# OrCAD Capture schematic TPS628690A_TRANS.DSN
size D; title: TPS628690A 2.4-V to 5.5-V Input, 6-A Synchronous Step-Down; rev: 1.1; note: Datasheet: SLVSFS3A        EVM: SLUUC88A
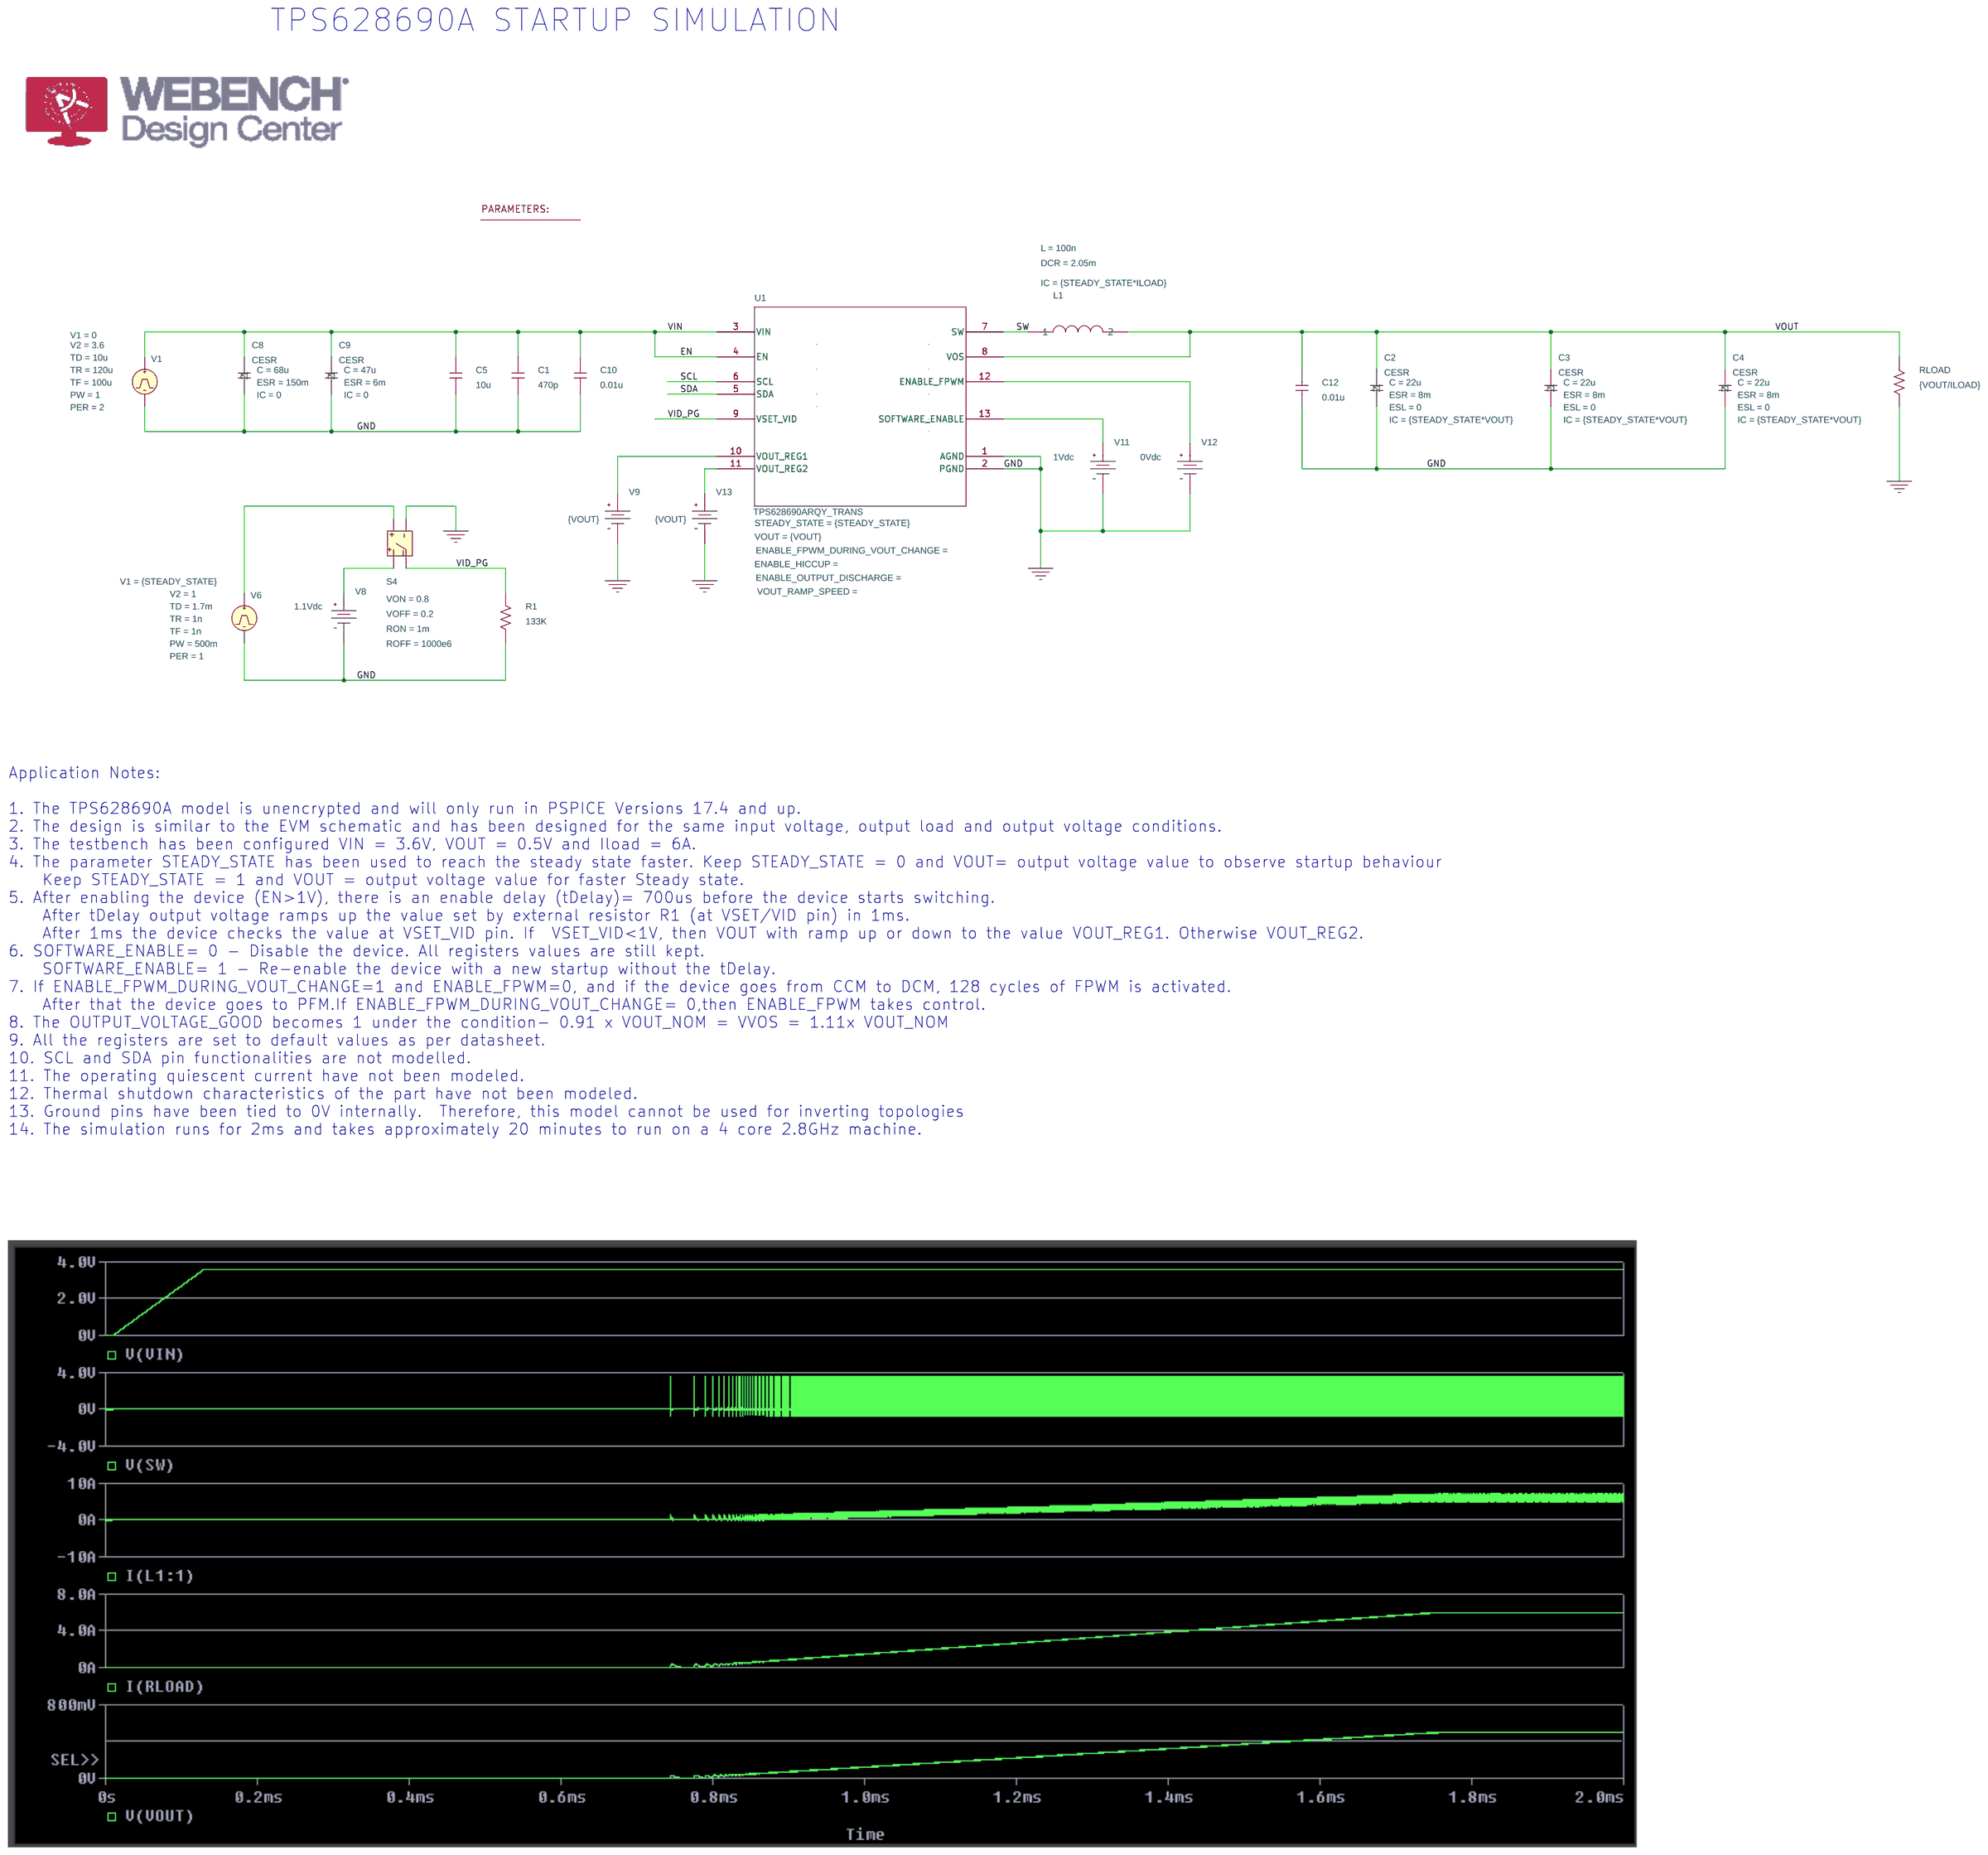
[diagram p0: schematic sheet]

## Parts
6  PARAM
C1  470p  [RAD/CK05]
C2  CESR
C3  CESR
C4  CESR
C5  10u  [RAD/CK05]
C8  CESR
C9  CESR
C10  0.01u  [RAD/CK05]
C12  0.01u  [RAD/CK05]
L1  LDCR
R1  133K  [AX/RC05]
RLOAD  {VOUT/ILOAD}  [AX/RC05]
S4  S
U1  TPS628690ARQY_TRANS  [RQY0009A-MFG]
V1  VPULSE
V6  VPULSE
V8  VDC
V9  VDC
V11  VDC
V12  VDC
V13  VDC

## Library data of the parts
6 = PARAM: STEADY_STATE: 0; VOUT: 0.5
C1 C5 C10 C12 = C
C2 = CESR_4: C: 22u; ESL: 0; ESR: 8m; IC: {STEADY_STATE*VOUT}; PSpiceTemplate: X^@REFDES %1 %2 @MODEL PARAMS: ?C|C=@C||C=10U| ?ESR|ESR=@ESR||ESR=2M| ?ESL|ESL=@ESL||ESL=1N| ?IC|IC=@IC||IC=0|
C3 = CESR_3: C: 22u; ESL: 0; ESR: 8m; IC: {STEADY_STATE*VOUT}; PSpiceTemplate: X^@REFDES %1 %2 @MODEL PARAMS: ?C|C=@C||C=10U| ?ESR|ESR=@ESR||ESR=2M| ?ESL|ESL=@ESL||ESL=1N| ?IC|IC=@IC||IC=0|
C4 = CESR: C: 22u; ESL: 0; ESR: 8m; IC: {STEADY_STATE*VOUT}; PSpiceTemplate: X^@REFDES %1 %2 @MODEL PARAMS: ?C|C=@C||C=10U| ?ESR|ESR=@ESR||ESR=2M| ?ESL|ESL=@ESL||ESL=1N| ?IC|IC=@IC||IC=0|
C8 = CESR_1: C: 68u; ESR: 150m; IC: 0; PSpiceTemplate: X^@REFDES %1 %2 @MODEL PARAMS: ?C|C=@C||C=10U| ?ESR|ESR=@ESR||ESR=2M| ?ESL|ESL=@ESL||ESL=1N| ?IC|IC=@IC||IC=0|
C9 = CESR_2: C: 47u; ESR: 6m; IC: 0; PSpiceTemplate: X^@REFDES %1 %2 @MODEL PARAMS: ?C|C=@C||C=10U| ?ESR|ESR=@ESR||ESR=2M| ?ESL|ESL=@ESL||ESL=1N| ?IC|IC=@IC||IC=0|
L1 = LDCR: DCR: 2.05m; IC: {STEADY_STATE*ILOAD}; L: 100n
R1 RLOAD = R
S4 = S: ROFF: 1000e6; RON: 1m; VOFF: 0.2; VON: 0.8
U1 = TPS628690ARQY_TRANS: STEADY_STATE: {STEADY_STATE}; VOUT: {VOUT}
V1 = VPULSE: PER: 2; PW: 1; TD: 10u; TF: 100u; TR: 120u; V1: 0; V2: 3.6
V6 = VPULSE: PER: 1; PW: 500m; TD: 1.7m; TF: 1n; TR: 1n; V1: {STEADY_STATE}; V2: 1
V8 = VDC: DC: 1.1Vdc
V9 V13 = VDC: DC: {VOUT}
V11 = VDC: DC: 1Vdc
V12 = VDC: DC: 0Vdc

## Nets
0: C1.1 C2.2 C3.2 C4.2 C5.1 C8.2 C9.2 C10.1 C12.1 R1.1 RLOAD.2 S4.1(2) U1.1(AGND) U1.2(PGND) V1.2(-) V6.2(-) V8.1(-) V9.1(-) V11.1(-) V12.1(-) V13.1(-)
EN: C1.2 C5.2 C8.1 C9.1 C10.2 U1.3(VIN) U1.4(EN) V1.1(+)
SCL: U1.6(SCL)
SDA: U1.5(SDA)
SW: L1.1 U1.7(SW)
VID_PG: R1.2 S4.3(4) U1.9(VSET_VID)
VOUT: C2.1 C3.1 C4.1 C12.2 L1.2 RLOAD.1 U1.8(VOS)
N16772220: U1.12(ENABLE_FPWM) V12.0(+)
N16772452: U1.13(SOFTWARE_ENABLE) V11.0(+)
N16772536: U1.10(VOUT_REG1) V9.0(+)
N16772656: S4.0(1) V6.1(+)
N16772756: S4.2(3) V8.0(+)
N16779626: U1.11(VOUT_REG2) V13.0(+)

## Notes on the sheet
- TPS628690A STARTUP SIMULATION
- Application Notes:
  1. The TPS628690A model is unencrypted and will only run in PSPICE Versions 17.4 and up.
  2. The design is similar to the EVM schematic and has been designed for the same input voltage, output load and output voltage conditions.
  3. The testbench has been configured VIN = 3.6V, VOUT = 0.5V and Iload = 6A.
  4. The parameter STEADY_STATE has been used to reach the steady state faster. Keep STEADY_STATE = 0 and VOUT= output voltage value to observe startup behaviour
      Keep STEADY_STATE = 1 and VOUT = output voltage value for faster Steady state.
  5. After enabling the device (EN>1V), there is an enable delay (tDelay)= 700us before the device starts switching.
      After tDelay output voltage ramps up the value set by external resistor R1 (at VSET/VID pin) in 1ms.
      After 1ms the device checks the value at VSET_VID pin. If  VSET_VID<1V, then VOUT with ramp up or down to the value VOUT_REG1. Otherwise VOUT_REG2.
  6. SOFTWARE_ENABLE= 0 - Disable the device. All registers values are still kept.
      SOFTWARE_ENABLE= 1 - Re-enable the device with a new startup without the tDelay.
  7. If ENABLE_FPWM_DURING_VOUT_CHANGE=1 and ENABLE_FPWM=0, and if the device goes from CCM to DCM, 128 cycles of FPWM is activated.
      After that the device goes to PFM.If ENABLE_FPWM_DURING_VOUT_CHANGE= 0,then ENABLE_FPWM takes control.
  8. The OUTPUT_VOLTAGE_GOOD becomes 1 under the condition- 0.91 x VOUT_NOM = VVOS = 1.11x VOUT_NOM
  9. All the registers are set to default values as per datasheet.
  10. SCL and SDA pin functionalities are not modelled.
  11. The operating quiescent current have not been modeled.
  12. Thermal shutdown characteristics of the part have not been modeled.
  13. Ground pins have been tied to 0V internally.  Therefore, this model cannot be used for inverting topologies
  14. The simulation runs for 2ms and takes approximately 20 minutes to run on a 4 core 2.8GHz machine.
